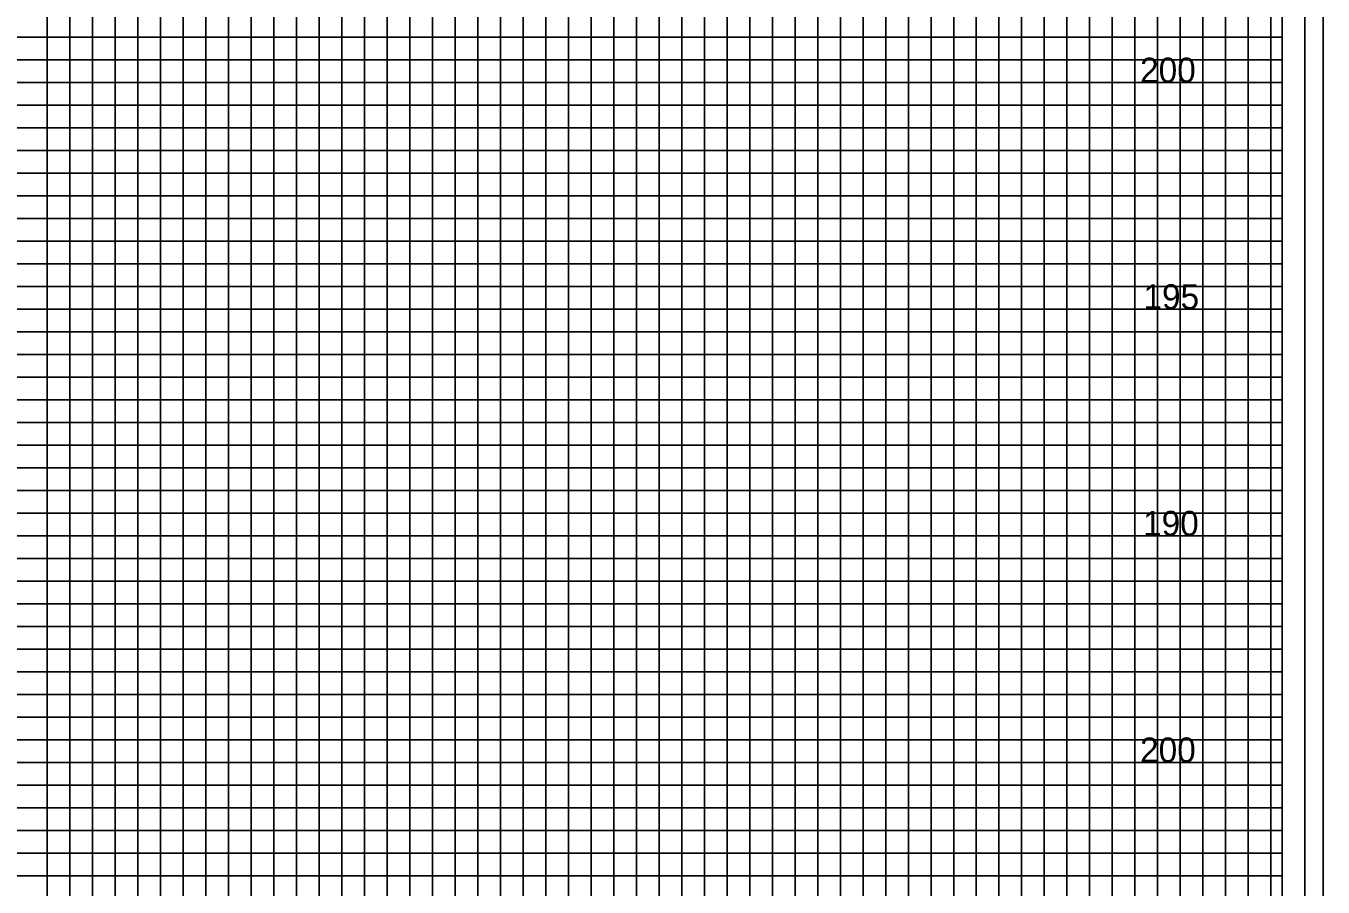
# Model space of a CAD drawing. Extents: x -4 to 103, y -2 to 209.
# Drawn here: x 74.78 to 103.4, y 103.08 to 122.08 of the extents above; entities that cross this region are included whole.
import ezdxf

# ---------------------------------------------------------------- set-up
doc = ezdxf.new("R2010")
doc.units = 0
for name, color, linetype in [('Exist XS Ground Line', 7, 'Continuous'), ('Old_Level_10', 7, 'Continuous'), ('Old_Level_5', 7, 'Continuous'), ('Old_Level_8', 7, 'Continuous'), ('Prop XS Dump Level', 7, 'Continuous'), ('Prop XS Finish Grade', 7, 'Continuous'), ('Prop XS Label Text', 7, 'Continuous')]:
    doc.layers.add(name, color=color, linetype=linetype)

msp = doc.modelspace()

# ---------------------------------------------------------------- linework, layer by layer
at = {"layer": 'Exist XS Ground Line'}
msp.add_lwpolyline([(103, 136.825), (-2.8, 136.825), (-2.8, 69.825), (103, 69.825)], close=True, dxfattribs=at)
at = {"layer": 'Old_Level_10'}
for p, q in [((91.25, 70.825), (91.25, 134.25)), ((93.75, 70.825), (93.75, 134.25)), ((96.25, 70.825), (96.25, 134.25)), ((98.75, 70.825), (98.75, 134.25)), ((101.25, 70.825), (101.25, 134.25)), ((76.25, 70.825), (76.25, 132.825)), ((78.75, 70.825), (78.75, 132.825)), ((81.25, 70.825), (81.25, 132.825)), ((83.75, 70.825), (83.75, 132.825)), ((86.25, 70.825), (86.25, 132.825)), ((88.75, 70.825), (88.75, 132.825)), ((0, 120.825), (102.5, 120.825)), ((0, 118.325), (102.5, 118.325)), ((0, 115.825), (102.5, 115.825)), ((0, 113.325), (102.5, 113.325)), ((0, 110.825), (102.5, 110.825)), ((0, 108.325), (102.5, 108.325)), ((0, 105.825), (102.5, 105.825)), ((0, 103.325), (102.5, 103.325))]:
    msp.add_line(p, q, dxfattribs=at)
at = {"layer": 'Old_Level_5'}
msp.add_lwpolyline([(103.4, 138.225), (-3.5, 138.225), (-3.5, 68.4), (103.4, 68.4)], close=True, dxfattribs=at)
at = {"layer": 'Old_Level_8'}
for points in [[(91.25, 70.825), (91.25, 134.25), (93.75, 134.25), (93.75, 70.825)], [(96.25, 70.825), (96.25, 134.25), (98.75, 134.25), (98.75, 70.825)], [(101.25, 70.825), (101.25, 134.25)], [(76.25, 70.825), (76.25, 132.825), (78.75, 132.825), (78.75, 70.825)], [(81.25, 70.825), (81.25, 132.825), (83.75, 132.825), (83.75, 70.825)], [(86.25, 70.825), (86.25, 132.825), (88.75, 132.825), (88.75, 70.825)], [(0, 118.325), (102.5, 118.325), (102.5, 120.825), (0, 120.825)], [(0, 113.325), (102.5, 113.325), (102.5, 115.825), (0, 115.825)], [(0, 108.325), (102.5, 108.325), (102.5, 110.825), (0, 110.825)], [(0, 103.325), (102.5, 103.325), (102.5, 105.825), (0, 105.825)]]:
    msp.add_lwpolyline(points, dxfattribs=at)
at = {"layer": 'Prop XS Dump Level'}
msp.add_lwpolyline([(102.5, 135.825), (0, 135.825), (0, 70.825), (102.5, 70.825)], close=True, dxfattribs=at)
at = {"layer": 'Prop XS Finish Grade'}
for points in [[(90.25, 70.825), (90.25, 134.25), (90.75, 134.25), (90.75, 70.825)], [(91.75, 70.825), (91.75, 134.25), (92.25, 134.25), (92.25, 70.825)], [(92.75, 70.825), (92.75, 134.25), (93.25, 134.25), (93.25, 70.825)], [(94.25, 70.825), (94.25, 134.25), (94.75, 134.25), (94.75, 70.825)], [(95.25, 70.825), (95.25, 134.25), (95.75, 134.25), (95.75, 70.825)], [(96.75, 70.825), (96.75, 134.25), (97.25, 134.25), (97.25, 70.825)], [(97.75, 70.825), (97.75, 134.25), (98.25, 134.25), (98.25, 70.825)], [(99.25, 70.825), (99.25, 134.25), (99.75, 134.25), (99.75, 70.825)], [(100.25, 70.825), (100.25, 134.25)], [(100.25, 134.25), (100.75, 134.25), (100.75, 70.825), (101.75, 70.825), (101.75, 134.25), (102.25, 134.25), (102.25, 70.825)], [(75.25, 70.825), (75.25, 132.825), (75.75, 132.825), (75.75, 70.825)], [(76.75, 70.825), (76.75, 132.825), (77.25, 132.825), (77.25, 70.825)], [(77.75, 70.825), (77.75, 132.825), (78.25, 132.825), (78.25, 70.825)], [(79.25, 70.825), (79.25, 132.825), (79.75, 132.825), (79.75, 70.825)], [(80.25, 70.825), (80.25, 132.825), (80.75, 132.825), (80.75, 70.825)], [(81.75, 70.825), (81.75, 132.825), (82.25, 132.825), (82.25, 70.825)], [(82.75, 70.825), (82.75, 132.825), (83.25, 132.825), (83.25, 70.825)], [(84.25, 70.825), (84.25, 132.825), (84.75, 132.825), (84.75, 70.825)], [(85.25, 70.825), (85.25, 132.825), (85.75, 132.825), (85.75, 70.825)], [(86.75, 70.825), (86.75, 132.825), (87.25, 132.825), (87.25, 70.825)], [(87.75, 70.825), (87.75, 132.825), (88.25, 132.825), (88.25, 70.825)], [(89.25, 70.825), (89.25, 132.825), (89.75, 132.825), (89.75, 70.825)], [(0, 121.325), (102.5, 121.325), (102.5, 121.825), (0, 121.825)], [(0, 119.825), (102.5, 119.825), (102.5, 120.325), (0, 120.325)], [(0, 118.825), (102.5, 118.825), (102.5, 119.325), (0, 119.325)], [(0, 117.325), (102.5, 117.325), (102.5, 117.825), (0, 117.825)], [(0, 116.325), (102.5, 116.325), (102.5, 116.825), (0, 116.825)], [(0, 114.825), (102.5, 114.825), (102.5, 115.325), (0, 115.325)], [(0, 113.825), (102.5, 113.825), (102.5, 114.325), (0, 114.325)], [(0, 112.325), (102.5, 112.325), (102.5, 112.825), (0, 112.825)], [(0, 111.325), (102.5, 111.325), (102.5, 111.825), (0, 111.825)], [(0, 109.825), (102.5, 109.825), (102.5, 110.325), (0, 110.325)], [(0, 108.825), (102.5, 108.825), (102.5, 109.325), (0, 109.325)], [(0, 107.325), (102.5, 107.325), (102.5, 107.825), (0, 107.825)], [(0, 106.325), (102.5, 106.325), (102.5, 106.825), (0, 106.825)], [(0, 104.825), (102.5, 104.825), (102.5, 105.325), (0, 105.325)], [(0, 103.825), (102.5, 103.825), (102.5, 104.325), (0, 104.325)]]:
    msp.add_lwpolyline(points, dxfattribs=at)

# ---------------------------------------------------------------- texts
at = {"layer": 'Prop XS Label Text'}
for s, p in [('200', (99.3638, 120.825)), ('195', (99.4383, 115.825)), ('190', (99.4296, 110.825)), ('200', (99.3638, 105.825))]:
    msp.add_text(s, height=0.55, dxfattribs=at).set_placement(p)

doc.saveas('drawing.dxf')
